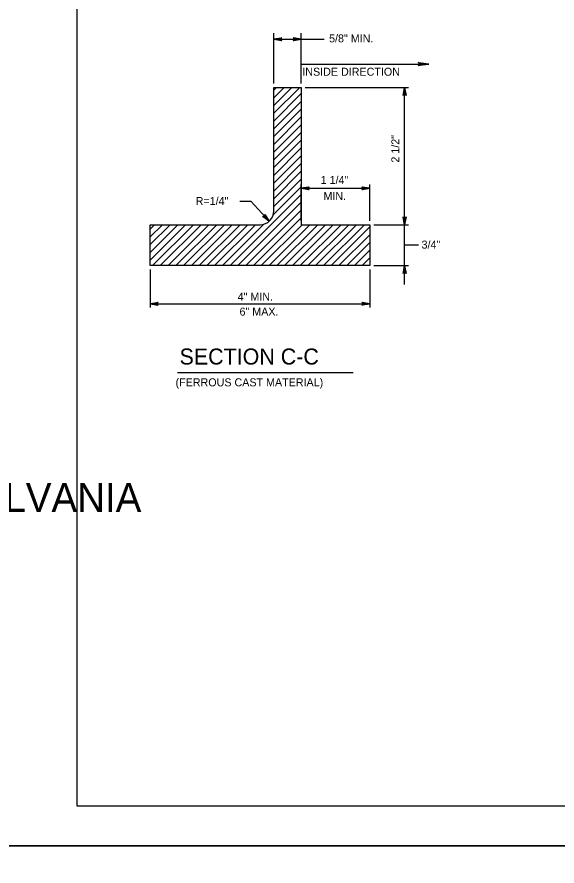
# Model space of a CAD drawing. Extents: x 2087776 to 2104538, y 970919 to 982612.
# Drawn here: x 2096108 to 2096771, y 974792 to 975836 of the extents above; entities that cross this region are included whole.
import ezdxf

# ---------------------------------------------------------------- set-up
doc = ezdxf.new("R2010")
doc.units = 0
doc.layers.add('1', color=7, linetype='Continuous')
doc.layers.add('PLT-BNDY', color=7, linetype='Continuous')

msp = doc.modelspace()

# ---------------------------------------------------------------- linework, layer by layer
at = {"layer": '1'}
for p, q in [((2096423, 975754.2), (2096423, 975816)), ((2096423, 975808.6), (2096456.8, 975808.6)), ((2096456.8, 975754.2), (2096456.8, 975816)), ((2096456.8, 975808.6), (2096485.1, 975808.6)), ((2096456.8, 975778.1), (2096613.5, 975778.1)), ((2096461.5, 975749.4), (2096588.4, 975749.4)), ((2096583.6, 975507.3), (2096583.6, 975749.4)), ((2096456.8, 975585.4), (2096456.8, 975630.2)), ((2096541.1, 975585.4), (2096541.1, 975630.2)), ((2096456.8, 975625.5), (2096541.1, 975625.5)), ((2096545.8, 975580.7), (2096588.4, 975580.7)), ((2096583.6, 975556), (2096601, 975556)), ((2096271.2, 975525.7), (2096271.2, 975478.8)), ((2096541.1, 975525.7), (2096541.1, 975478.8)), ((2096545.8, 975530.4), (2096588.4, 975530.4)), ((2096271.2, 975483.5), (2096541.1, 975483.5)), ((2096305, 975399.1), (2096520.7, 975399.1))]:
    msp.add_line(p, q, dxfattribs=at)
for points in [[(2098759.9, 974866.2), (2098759.9, 976716.6), (2096181.2, 976716.6), (2096181.2, 974866.2), (2098759.9, 974866.2), (2098759.9, 974952.7), (2098103.8, 974952.7), (2098103.8, 975164.9), (2098759.9, 975164.9), (2098759.9, 975259.9), (2098103.8, 975259.9), (2098103.8, 974866.2), (2098362.3, 974866.2), (2098362.3, 974952.7), (2098362.3, 974866.2), (2098614.9, 974866.2), (2098614.9, 974952.7), (2098614.9, 974912.3), (2098759.9, 974912.3)], [(2096423, 975808.6), (2096432.8, 975810.5), (2096432.4, 975810.2), (2096432.1, 975809.9), (2096431.9, 975809.6), (2096431.7, 975809.3), (2096431.6, 975809), (2096431.6, 975808.6), (2096431.6, 975808.3), (2096431.7, 975808), (2096431.9, 975807.6), (2096432.1, 975807.3), (2096432.4, 975807.1), (2096432.8, 975806.8), (2096423, 975808.6), (2096432.4, 975807.1), (2096432.1, 975807.3), (2096423, 975808.6), (2096431.9, 975807.6), (2096431.7, 975808), (2096423, 975808.6), (2096431.6, 975808.3), (2096431.6, 975808.6), (2096423, 975808.6), (2096431.6, 975809), (2096431.7, 975809.3), (2096423, 975808.6), (2096431.9, 975809.6), (2096432.1, 975809.9), (2096423, 975808.6), (2096432.4, 975810.2)], [(2096456.8, 975808.6), (2096447, 975806.8), (2096447.4, 975807.1), (2096447.7, 975807.3), (2096447.9, 975807.6), (2096448.1, 975808), (2096448.2, 975808.3), (2096448.2, 975808.6), (2096448.2, 975809), (2096448.1, 975809.3), (2096447.9, 975809.6), (2096447.7, 975809.9), (2096447.4, 975810.2), (2096447, 975810.5), (2096456.8, 975808.6), (2096447.4, 975810.2), (2096447.7, 975809.9), (2096456.8, 975808.6), (2096447.9, 975809.6), (2096448.1, 975809.3), (2096456.8, 975808.6), (2096448.2, 975809), (2096448.2, 975808.6), (2096456.8, 975808.6), (2096448.2, 975808.3), (2096448.1, 975808), (2096456.8, 975808.6), (2096447.9, 975807.6), (2096447.7, 975807.3), (2096456.8, 975808.6), (2096447.4, 975807.1)], [(2096601.3, 975779.7), (2096601.7, 975778.8), (2096613.5, 975778.1), (2096601.3, 975779.7), (2096600.6, 975780.2), (2096613.5, 975778.1), (2096601.7, 975777.5), (2096601.3, 975776.7), (2096613.5, 975778.1), (2096600.6, 975776.1), (2096601.3, 975776.7)], [(2096423, 975597.6), (2096423, 975749.4), (2096456.8, 975749.4), (2096456.8, 975580.7)], [(2096423, 975717.6), (2096454.9, 975749.4)], [(2096423, 975727.1), (2096445.3, 975749.4)], [(2096423, 975736.7), (2096435.8, 975749.4)], [(2096423, 975746.2), (2096426.2, 975749.4)], [(2096583.6, 975749.4), (2096585.5, 975739.6), (2096585.2, 975740), (2096584.9, 975740.4), (2096584.6, 975740.6), (2096584.3, 975740.8), (2096584, 975740.8), (2096583.6, 975740.9), (2096583.3, 975740.8), (2096583, 975740.8), (2096582.6, 975740.6), (2096582.3, 975740.4), (2096582.1, 975740), (2096581.8, 975739.6), (2096583.6, 975749.4), (2096582.1, 975740), (2096582.3, 975740.4), (2096583.6, 975749.4), (2096582.6, 975740.6), (2096583, 975740.8), (2096583.6, 975749.4), (2096583.3, 975740.8), (2096583.6, 975740.9), (2096583.6, 975749.4), (2096584, 975740.8), (2096584.3, 975740.8), (2096583.6, 975749.4), (2096584.6, 975740.6), (2096584.9, 975740.4), (2096583.6, 975749.4), (2096585.2, 975740)], [(2096423, 975708), (2096456.8, 975741.8)], [(2096423, 975698.5), (2096456.8, 975732.2)], [(2096423, 975688.9), (2096456.8, 975722.7)], [(2096423, 975679.4), (2096456.8, 975713.1)], [(2096423, 975669.8), (2096456.8, 975703.6)], [(2096423, 975660.3), (2096456.8, 975694)], [(2096423, 975650.8), (2096456.8, 975684.5)], [(2096423, 975641.2), (2096456.8, 975675)], [(2096423, 975631.7), (2096456.8, 975665.4)], [(2096423, 975622.1), (2096456.8, 975655.9)], [(2096423, 975612.6), (2096456.8, 975646.3)], [(2096423, 975603), (2096456.8, 975636.8)], [(2096422.3, 975592.8), (2096456.8, 975627.2)], [(2096456.8, 975625.5), (2096466.6, 975627.3), (2096466.2, 975627), (2096465.8, 975626.8), (2096465.6, 975626.4), (2096465.4, 975626.1), (2096465.4, 975625.8), (2096465.3, 975625.5), (2096465.4, 975625.1), (2096465.4, 975624.8), (2096465.6, 975624.5), (2096465.8, 975624.1), (2096466.2, 975623.9), (2096466.6, 975623.6), (2096456.8, 975625.5), (2096466.2, 975623.9), (2096465.8, 975624.1), (2096456.8, 975625.5), (2096465.6, 975624.5), (2096465.4, 975624.8), (2096456.8, 975625.5), (2096465.4, 975625.1), (2096465.3, 975625.5), (2096456.8, 975625.5), (2096465.4, 975625.8), (2096465.4, 975626.1), (2096456.8, 975625.5), (2096465.6, 975626.4), (2096465.8, 975626.8), (2096456.8, 975625.5), (2096466.2, 975627)], [(2096541.1, 975625.5), (2096531.3, 975623.6), (2096531.7, 975623.9), (2096532.1, 975624.1), (2096532.3, 975624.5), (2096532.5, 975624.8), (2096532.5, 975625.1), (2096532.6, 975625.5), (2096532.5, 975625.8), (2096532.5, 975626.1), (2096532.3, 975626.4), (2096532.1, 975626.8), (2096531.7, 975627), (2096531.3, 975627.3), (2096541.1, 975625.5), (2096531.7, 975627), (2096532.1, 975626.8), (2096541.1, 975625.5), (2096532.3, 975626.4), (2096532.5, 975626.1), (2096541.1, 975625.5), (2096532.5, 975625.8), (2096532.6, 975625.5), (2096541.1, 975625.5), (2096532.5, 975625.1), (2096532.5, 975624.8), (2096541.1, 975625.5), (2096532.3, 975624.5), (2096532.1, 975624.1), (2096541.1, 975625.5), (2096531.7, 975623.9)], [(2096369.5, 975530.4), (2096456.8, 975617.7)], [(2096381.4, 975609.6), (2096394.9, 975609.6), (2096417.3, 975584.9)], [(2096379.1, 975530.4), (2096456.8, 975608.2)], [(2096388.6, 975530.4), (2096456.8, 975598.6)], [(2096398.1, 975530.4), (2096456.8, 975589.1)], [(2096417.3, 975584.9), (2096409.4, 975590.9), (2096409.8, 975590.8), (2096410.3, 975590.7), (2096410.7, 975590.8), (2096411, 975590.9), (2096411.3, 975591.1), (2096411.6, 975591.3), (2096411.8, 975591.5), (2096412, 975591.8), (2096412.1, 975592.1), (2096412.2, 975592.5), (2096412.2, 975593), (2096412.1, 975593.4), (2096417.3, 975584.9), (2096412.2, 975593), (2096412.2, 975592.5), (2096417.3, 975584.9), (2096412.1, 975592.1), (2096412, 975591.8), (2096417.3, 975584.9), (2096411.8, 975591.5), (2096411.6, 975591.3), (2096417.3, 975584.9), (2096411.3, 975591.1), (2096411, 975590.9), (2096417.3, 975584.9), (2096410.7, 975590.8), (2096410.3, 975590.7), (2096417.3, 975584.9), (2096409.8, 975590.8)], [(2096583.6, 975580.7), (2096581.8, 975590.5), (2096582.1, 975590.1), (2096582.3, 975589.7), (2096582.6, 975589.5), (2096583, 975589.3), (2096583.3, 975589.3), (2096583.6, 975589.2), (2096584, 975589.3), (2096584.3, 975589.3), (2096584.6, 975589.5), (2096584.9, 975589.7), (2096585.2, 975590.1), (2096585.5, 975590.5), (2096583.6, 975580.7), (2096585.2, 975590.1), (2096584.9, 975589.7), (2096583.6, 975580.7), (2096584.6, 975589.5), (2096584.3, 975589.3), (2096583.6, 975580.7), (2096584, 975589.3), (2096583.6, 975589.2), (2096583.6, 975580.7), (2096583.3, 975589.3), (2096583, 975589.3), (2096583.6, 975580.7), (2096582.6, 975589.5), (2096582.3, 975589.7), (2096583.6, 975580.7), (2096582.1, 975590.1)], [(2096456.8, 975580.7), (2096541.1, 975580.7), (2096541.1, 975530.4), (2096271.2, 975530.4), (2096271.2, 975580.7), (2096406.2, 975580.7)], [(2096271.2, 975537.1), (2096314.8, 975580.7)], [(2096271.2, 975546.6), (2096305.3, 975580.7)], [(2096271.2, 975556.2), (2096295.7, 975580.7)], [(2096271.2, 975565.7), (2096286.2, 975580.7)], [(2096271.2, 975575.3), (2096276.6, 975580.7)], [(2096274.1, 975530.4), (2096324.3, 975580.7)], [(2096283.6, 975530.4), (2096333.9, 975580.7)], [(2096293.2, 975530.4), (2096343.4, 975580.7)], [(2096302.7, 975530.4), (2096353, 975580.7)], [(2096312.2, 975530.4), (2096362.5, 975580.7)], [(2096321.8, 975530.4), (2096372.1, 975580.7)], [(2096331.3, 975530.4), (2096381.6, 975580.7)], [(2096340.9, 975530.4), (2096391.1, 975580.7)], [(2096350.4, 975530.4), (2096400.7, 975580.7)], [(2096360, 975530.4), (2096410.9, 975581.4)], [(2096407.7, 975530.4), (2096458, 975580.7)], [(2096417.2, 975530.4), (2096467.5, 975580.7)], [(2096426.8, 975530.4), (2096477, 975580.7)], [(2096436.3, 975530.4), (2096486.6, 975580.7)], [(2096445.9, 975530.4), (2096496.1, 975580.7)], [(2096455.4, 975530.4), (2096505.7, 975580.7)], [(2096465, 975530.4), (2096515.2, 975580.7)], [(2096474.5, 975530.4), (2096524.8, 975580.7)], [(2096484, 975530.4), (2096534.3, 975580.7)], [(2096493.6, 975530.4), (2096541.1, 975578)], [(2096503.1, 975530.4), (2096541.1, 975568.4)], [(2096512.7, 975530.4), (2096541.1, 975558.9)], [(2096522.2, 975530.4), (2096541.1, 975549.3)], [(2096531.8, 975530.4), (2096541.1, 975539.8)], [(2096583.6, 975530.4), (2096585.5, 975520.7), (2096585.2, 975521), (2096584.9, 975521.4), (2096584.6, 975521.6), (2096584.3, 975521.8), (2096584, 975521.9), (2096583.6, 975521.9), (2096583.3, 975521.9), (2096583, 975521.8), (2096582.6, 975521.6), (2096582.3, 975521.4), (2096582.1, 975521), (2096581.8, 975520.7), (2096583.6, 975530.4), (2096582.1, 975521), (2096582.3, 975521.4), (2096583.6, 975530.4), (2096582.6, 975521.6), (2096583, 975521.8), (2096583.6, 975530.4), (2096583.3, 975521.9), (2096583.6, 975521.9), (2096583.6, 975530.4), (2096584, 975521.9), (2096584.3, 975521.8), (2096583.6, 975530.4), (2096584.6, 975521.6), (2096584.9, 975521.4), (2096583.6, 975530.4), (2096585.2, 975521)], [(2096271.2, 975483.5), (2096281, 975485.3), (2096280.6, 975485.1), (2096280.2, 975484.8), (2096280, 975484.5), (2096279.8, 975484.2), (2096279.8, 975483.8), (2096279.7, 975483.5), (2096279.8, 975483.2), (2096279.8, 975482.8), (2096280, 975482.5), (2096280.2, 975482.2), (2096280.6, 975481.9), (2096281, 975481.7), (2096271.2, 975483.5), (2096280.6, 975481.9), (2096280.2, 975482.2), (2096271.2, 975483.5), (2096280, 975482.5), (2096279.8, 975482.8), (2096271.2, 975483.5), (2096279.8, 975483.2), (2096279.7, 975483.5), (2096271.2, 975483.5), (2096279.8, 975483.8), (2096279.8, 975484.2), (2096271.2, 975483.5), (2096280, 975484.5), (2096280.2, 975484.8), (2096271.2, 975483.5), (2096280.6, 975485.1)], [(2096541.1, 975483.5), (2096531.3, 975481.7), (2096531.7, 975481.9), (2096532.1, 975482.2), (2096532.3, 975482.5), (2096532.5, 975482.8), (2096532.5, 975483.2), (2096532.6, 975483.5), (2096532.5, 975483.8), (2096532.5, 975484.2), (2096532.3, 975484.5), (2096532.1, 975484.8), (2096531.7, 975485.1), (2096531.3, 975485.3), (2096541.1, 975483.5), (2096531.7, 975485.1), (2096532.1, 975484.8), (2096541.1, 975483.5), (2096532.3, 975484.5), (2096532.5, 975484.2), (2096541.1, 975483.5), (2096532.5, 975483.8), (2096532.6, 975483.5), (2096541.1, 975483.5), (2096532.5, 975483.2), (2096532.5, 975482.8), (2096541.1, 975483.5), (2096532.3, 975482.5), (2096532.1, 975482.2), (2096541.1, 975483.5), (2096531.7, 975481.9)]]:
    msp.add_lwpolyline(points, dxfattribs=at)
msp.add_arc((2096406.2, 975597.6), 16.9, 270, 360, dxfattribs=at)
at = {"layer": 'PLT-BNDY'}
for points in [[(2096053.2, 976765.8), (2098812.4, 976765.8), (2098812.4, 974817), (2096053.2, 974817)], [(2096053.2, 974817), (2098812.4, 974817), (2098812.4, 972868.2), (2096053.2, 972868.2)]]:
    msp.add_lwpolyline(points, close=True, dxfattribs=at)

# ---------------------------------------------------------------- texts
at = {"layer": '1'}
for s, height, p in [('5/8" MIN.', 9.84, (2096491, 975804.8)), ('INSIDE DIRECTION', 9.843, (2096458.1, 975763.8)), ('1 1/4"', 9.84, (2096480.6, 975630.7)), ('MIN.', 9.84, (2096484.1, 975611)), ('R=1/4"', 9.84, (2096327.1, 975604.9)), ('3/4"', 9.84, (2096604.6, 975551.3)), ('4" MIN.', 9.84, (2096378.7, 975487.3)), ('6" MAX.', 9.84, (2096381, 975468.9)), ('SECTION C-C', 19.685, (2096307.3, 975408.8)), ('(FERROUS CAST MATERIAL)', 9.843, (2096302.4, 975382)), ('COMMONWEALTH OF PENNSYLVANIA', 35.379, (2095387.7, 975227.6))]:
    msp.add_text(s, height=height, dxfattribs=at).set_placement(p)
msp.add_text('2 1/2"', height=9.84, rotation=90, dxfattribs=at).set_placement((2096577.3, 975657))

doc.saveas('drawing.dxf')
